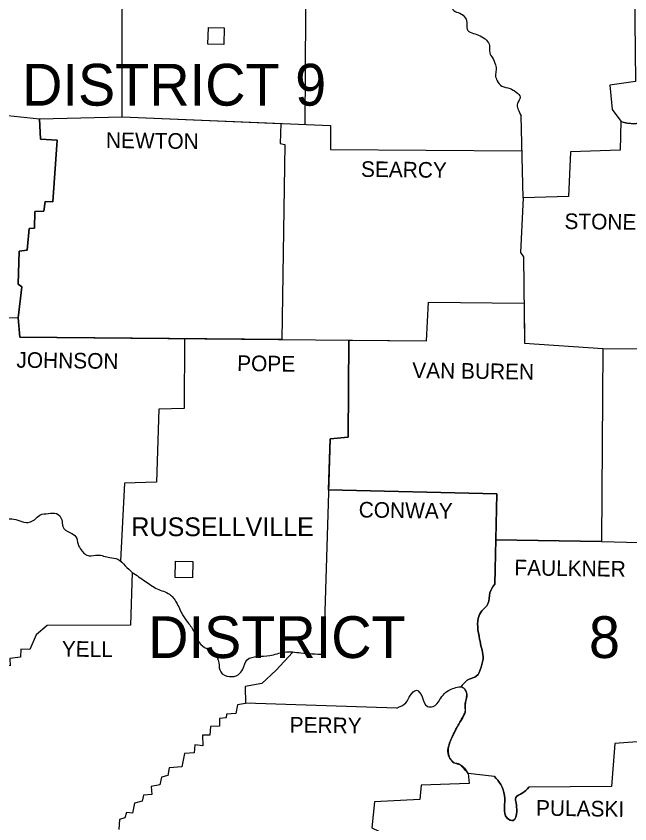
# Model space of a CAD drawing. Extents: x 840176 to 859715, y 1589036 to 1600368.
# Drawn here: x 854218 to 855136, y 1597581 to 1598788 of the extents above; entities that cross this region are included whole.
import ezdxf

# ---------------------------------------------------------------- set-up
doc = ezdxf.new("R2010")
doc.units = 0
doc.layers.add('DSN_DRFT_Border', color=7, linetype='Continuous')
doc.layers.add('SHET_Stamp-Prelim', color=7, linetype='Continuous')

msp = doc.modelspace()

# ---------------------------------------------------------------- linework, layer by layer
at = {"layer": 'DSN_DRFT_Border'}
msp.add_line((854885, 1597788.1), (854883.1, 1597786), dxfattribs=at)
for points in [[(853989.1, 1598788.7), (854127.2, 1598784.3), (854130.3, 1598766.8), (854149.3, 1598766.2), (854148.7, 1598755.6), (854161.4, 1598752.2), (854162.7, 1598692.1), (854179.8, 1598688.4), (854181, 1598664.7), (854204.7, 1598661.6), (854205.9, 1598639.5), (854253.3, 1598634.4), (854376.5, 1598637.7), (854377.4, 1598959.2)], [(854651.9, 1598959.7), (854650, 1598626.2)], [(855150.4, 1598960.7), (855151.7, 1598827.2), (855142.7, 1598826.6), (855143.9, 1598690.3), (855105.9, 1598684.7), (855109.1, 1598648.3), (855122.1, 1598631.1), (855121.2, 1598587.9), (855046.8, 1598585.1), (855044, 1598518.5), (854976.2, 1598516.3), (854972.4, 1598434.8), (854976.5, 1598428.5), (854978.3, 1598299.1), (855095.1, 1598291.3), (855093.5, 1598002.8), (855186.9, 1598000.3), (855186.9, 1597706.5), (855113.4, 1597700.9), (855108.1, 1597636.8), (854984.6, 1597635.9)], [(853529.5, 1598628.3), (853633.9, 1598628), (853636.4, 1598663.8), (853674.1, 1598663.8), (853677.5, 1598722.3), (853891.3, 1598714.9), (853897.5, 1598731), (853987.6, 1598733), (853941.7, 1598604.7), (853932.7, 1598401.5), (853926.1, 1598401.2), (853923, 1598339.8), (853955.1, 1598337), (853960.1, 1598342), (854221.2, 1598337), (854224, 1598308.1)], [(854253.3, 1598634.4), (854254.5, 1598604.1), (854279.7, 1598602.8), (854273.1, 1598510.7), (854261.6, 1598511), (854259.5, 1598496.4), (854246.4, 1598496.1), (854245.8, 1598471.2), (854237.7, 1598470.6), (854234.9, 1598438.2), (854222.7, 1598436.6), (854221.2, 1598387.5), (854226.8, 1598383.4), (854221.2, 1598337)], [(854376.5, 1598637.7), (854688.3, 1598624.6), (854688, 1598588.8), (854974.4, 1598586.9)], [(854613.7, 1598627.7), (854612.7, 1598597.8), (854620.1, 1598596), (854615.4, 1598304.7)], [(854976.2, 1598516.3), (854973.1, 1598639.2)], [(854224, 1598308.1), (854831.8, 1598302.8), (854834.9, 1598360.7), (854977.5, 1598358.8)], [(854469.8, 1598306), (854469.2, 1598201.4), (854431.5, 1598200.7), (854428.1, 1598091.8), (854380.2, 1598089.9), (854374.4, 1597974)], [(854715.4, 1598303.8), (854714.4, 1598158.7), (854687.7, 1598156.2), (854677.7, 1597834.1)], [(855095.1, 1598291.3), (855376.7, 1598290.1), (855400.7, 1598301.3), (855399.1, 1598087.5), (855382.9, 1598080.3), (855368, 1598067.5), (855363.3, 1598062.6), (855362.4, 1598001.2), (855186.9, 1598000.3)], [(854685.3, 1598080.3), (854937, 1598074.1), (854933.8, 1597939)], [(854935.4, 1598005.3), (855093.5, 1598002.8)], [(854391.7, 1597956.7), (854389.2, 1597878), (854264.7, 1597877.4), (854248.2, 1597863.4), (854238.6, 1597841.6), (854225.2, 1597842.2), (854224.6, 1597830.1), (854208.7, 1597828.2), (854209.3, 1597817), (854130, 1597818.9), (854126.9, 1597810.2), (854094.2, 1597808.9), (854093.9, 1597712.9)], [(854631.4, 1597837.3), (854606.8, 1597810.8), (854585.6, 1597790.6), (854560.7, 1597786.5), (854561, 1597760.7), (854548.9, 1597759.1), (854546.7, 1597746.1), (854532.7, 1597744.8), (854532.1, 1597739.2), (854522.4, 1597738.6), (854522.1, 1597727.1), (854508.7, 1597726.4), (854507.8, 1597713.4), (854496.6, 1597713.4), (854497.2, 1597697.8), (854485.4, 1597699.1), (854484.5, 1597686.9), (854469.8, 1597686), (854465.8, 1597666.1), (854447.1, 1597664.5), (854445.2, 1597653.3), (854435.3, 1597650.8), (854432.8, 1597639.3), (854420.3, 1597636.8), (854421.3, 1597625), (854408.8, 1597623.7), (854406.7, 1597615), (854395.1, 1597611.9), (854392.3, 1597597), (854383.3, 1597597.9), (854380.8, 1597590.1), (854372.7, 1597587.3), (854371.8, 1597572.4)], [(854787.3, 1597754.1), (854561, 1597761.6)], [(854933.2, 1597651.8), (854894, 1597656.4), (854895.6, 1597641.5), (854823.7, 1597638.7), (854821.5, 1597617.5), (854754, 1597613.8), (854750.2, 1597575.2), (854760.2, 1597570.2), (854760.2, 1597545)]]:
    msp.add_lwpolyline(points, dxfattribs=at)
for points in [[(854505, 1598746), (854505.6, 1598770.9), (854529.3, 1598770.3), (854528.6, 1598745.4)], [(854455.8, 1597949.3), (854456.4, 1597973.6), (854482.3, 1597972.9), (854481.7, 1597948.7)]]:
    msp.add_lwpolyline(points, close=True, dxfattribs=at)
for points in [[(854891.5, 1598863.6), (854881.6, 1598855.8), (854873.2, 1598848.1), (854859.8, 1598838.4), (854858.2, 1598829.7), (854862.6, 1598821.3), (854866.9, 1598814.1), (854868.8, 1598804.2), (854872.5, 1598796.1), (854881.6, 1598792.3), (854889.7, 1598785.5), (854892.1, 1598775.9), (854893.4, 1598766.5), (854901.8, 1598762.2), (854911.7, 1598758.4), (854921.4, 1598751.9), (854925.8, 1598744.1), (854926.4, 1598733.2), (854930.4, 1598725.4), (854934.8, 1598715.2), (854935.7, 1598707.1), (854934.8, 1598699), (854937.3, 1598691.2), (854944.1, 1598683.4), (854956.6, 1598679.7), (854965.6, 1598674.4), (854971.8, 1598666.6), (854967.5, 1598657.6), (854968.4, 1598649.2), (854973.1, 1598639.2)], [(854102.3, 1598023), (854120.6, 1598028.9), (854133.7, 1598030.5), (854147.1, 1598028), (854160.8, 1598022.4), (854175.1, 1598024), (854186, 1598027.7), (854197.2, 1598034.9), (854209, 1598037), (854220.9, 1598034.9), (854233, 1598031.4), (854245.8, 1598035.5), (854253.5, 1598042.3), (854266.6, 1598044.8), (854278.4, 1598044.8), (854286.5, 1598035.5), (854288.1, 1598025.2), (854298.7, 1598016.2), (854307.7, 1598010), (854310.8, 1597998.8), (854315.5, 1597990.4), (854320.4, 1597984.8), (854327.6, 1597981.6), (854339.7, 1597982.6), (854358.4, 1597978.8), (854370.2, 1597976.4), (854381.4, 1597966.7), (854391.7, 1597956.7)], [(854391.7, 1597956.7), (854411, 1597943.7), (854429.1, 1597932.2), (854447.4, 1597924.1), (854457.7, 1597912.2), (854467, 1597893.3), (854475.1, 1597881.7), (854484.5, 1597867.4), (854491.9, 1597851.9), (854503.1, 1597842.8), (854515.3, 1597835.4), (854521.2, 1597821.7), (854524, 1597808), (854537.4, 1597801.1), (854550.1, 1597803.9), (854557, 1597812.3), (854563.8, 1597826.3), (854578.4, 1597831), (854597.4, 1597832.6), (854619.2, 1597837.6), (854643.8, 1597836.6), (854677.7, 1597834.1)], [(854933.8, 1597939), (854926.4, 1597926.2), (854923.6, 1597909.8), (854914.5, 1597899.2), (854908.9, 1597887.7), (854908.6, 1597871.5), (854911.1, 1597857.2), (854913.9, 1597843.8), (854916.4, 1597831), (854913.3, 1597815.1), (854906.1, 1597801.5), (854895.6, 1597797.4), (854885, 1597788.1)], [(854787.3, 1597754.1), (854800.6, 1597761.9), (854807.8, 1597773.4), (854816.5, 1597780.6), (854825.2, 1597770.6), (854833, 1597756.6), (854841.4, 1597756.3), (854851.7, 1597766.6), (854858.2, 1597775.3), (854866.6, 1597781.5), (854875.3, 1597784.6), (854884.4, 1597785.6), (854891.8, 1597775), (854889.3, 1597758.5), (854889.3, 1597747.9), (854883.4, 1597736.1), (854876.6, 1597724), (854869.7, 1597710.3), (854864.4, 1597695.9), (854865.4, 1597681.3), (854873.2, 1597672.3), (854881.6, 1597669.5), (854894, 1597656.4)], [(854933.2, 1597651.8), (854942.6, 1597639.9), (854948.2, 1597623.4), (854948.2, 1597604.8), (854952.2, 1597589.5), (854961.2, 1597586.1), (854966.5, 1597599.5), (854965.6, 1597612.2), (854965.3, 1597620.3), (854974.9, 1597626.9), (854984.6, 1597635.9)]]:
    msp.add_spline(points, degree=3, dxfattribs=at)
msp.add_open_spline([(855122.1, 1598631.1), (855123.9, 1598630.3), (855125.6, 1598629.6), (855127.5, 1598629.1), (855129.3, 1598628.7), (855131.1, 1598628.3), (855133, 1598628.1), (855134.8, 1598627.9), (855136.6, 1598627.8), (855138.5, 1598627.6), (855140.3, 1598627.5), (855142.1, 1598627.4), (855143.9, 1598627.4), (855145.1, 1598627.4), (855146.3, 1598627.9), (855147.4, 1598628.6), (855148.6, 1598629.3), (855149.7, 1598630.3), (855150.8, 1598631.1), (855151.9, 1598631.8), (855153, 1598632.4), (855154.2, 1598633), (855154.7, 1598633.2), (855155.3, 1598633.2), (855155.8, 1598633.1), (855156.3, 1598633), (855156.8, 1598632.8), (855157.3, 1598632.4), (855159.7, 1598630.3), (855161.5, 1598628.2), (855162.9, 1598625.6), (855163.6, 1598624.3), (855164.2, 1598623), (855164.8, 1598621.7), (855165.4, 1598620.4), (855166, 1598619.1), (855166.6, 1598617.8), (855168.2, 1598614.1), (855169.7, 1598610.5), (855171.3, 1598606.9), (855172.5, 1598604.2), (855173.7, 1598601.5), (855175, 1598598.9), (855175.7, 1598597.5), (855176.4, 1598596.3), (855177.2, 1598595), (855177.6, 1598594.4), (855178, 1598593.8), (855178.4, 1598593.1), (855178.8, 1598592.5), (855179.2, 1598591.9), (855179.7, 1598591.3), (855180.4, 1598590.4), (855181.3, 1598589.7), (855182.4, 1598589.2), (855183.5, 1598588.8), (855184.7, 1598588.4), (855185.8, 1598588.2), (855187, 1598587.9), (855188.2, 1598587.7), (855189.4, 1598587.4), (855190, 1598587.2), (855190.6, 1598587), (855191.2, 1598586.8), (855191.7, 1598586.6), (855192.3, 1598586.3), (855192.8, 1598586), (855194.7, 1598584.9), (855196.5, 1598583.6), (855198.2, 1598582.3), (855199, 1598581.6), (855199.8, 1598580.9), (855200.6, 1598580.1), (855201.4, 1598579.3), (855202.1, 1598578.5), (855202.7, 1598577.6), (855203.2, 1598576.9), (855203.5, 1598576.2), (855203.7, 1598575.4), (855204, 1598574.6), (855204.1, 1598573.7), (855204, 1598572.9), (855203.9, 1598571.7), (855203.6, 1598570.4), (855203.1, 1598569.3), (855202.9, 1598568.9), (855202.7, 1598568.6), (855202.4, 1598568.3), (855201.8, 1598567.5), (855201.1, 1598566.7), (855200.4, 1598566), (855199.6, 1598565.3), (855198.9, 1598564.6), (855198.1, 1598563.9), (855197.4, 1598563.2), (855196.6, 1598562.5), (855195.8, 1598561.8), (855195.1, 1598561.1), (855194.4, 1598560.3), (855193.7, 1598559.6), (855193.4, 1598559.2), (855193.1, 1598558.8), (855192.8, 1598558.5), (855191.8, 1598557.4), (855190.7, 1598556.4), (855189.7, 1598555.3), (855189.1, 1598554.6), (855188.6, 1598553.9), (855188.1, 1598553), (855187.9, 1598552.6), (855187.8, 1598552.3), (855187.7, 1598551.8), (855187.5, 1598551.4), (855187.5, 1598551), (855187.5, 1598550.5), (855187.5, 1598549.7), (855187.6, 1598548.8), (855187.7, 1598547.9), (855187.9, 1598547), (855188.1, 1598546.1), (855188.3, 1598545.3), (855188.6, 1598544.4), (855188.9, 1598543.5), (855189.1, 1598542.6), (855189.3, 1598541.7), (855189.5, 1598540.9), (855189.7, 1598540), (855190.1, 1598537.6), (855190.4, 1598535.2), (855190.8, 1598532.8), (855191.2, 1598530.4), (855191.5, 1598528), (855191.8, 1598525.6), (855192.4, 1598521.2), (855192.9, 1598516.6), (855191.8, 1598512.3), (855190.8, 1598508), (855189.5, 1598503.8), (855188.4, 1598499.5), (855187.5, 1598495.8), (855186.5, 1598492.1), (855185.6, 1598488.3), (855185.4, 1598487.4), (855185.3, 1598486.6), (855185.3, 1598485.7), (855185.3, 1598484.8), (855185.4, 1598484), (855185.6, 1598483.1), (855185.9, 1598482.2), (855186.2, 1598481.4), (855186.7, 1598480.6), (855186.9, 1598480.1), (855187.2, 1598479.7), (855187.4, 1598479.3), (855187.7, 1598478.8), (855188.1, 1598478.4), (855188.4, 1598478), (855188.7, 1598477.6), (855189.1, 1598477.4), (855189.5, 1598477.1), (855189.9, 1598476.9), (855190.4, 1598476.7), (855190.8, 1598476.7), (855191.7, 1598476.6), (855192.6, 1598476.7), (855193.5, 1598477.1), (855195.3, 1598478), (855197, 1598478.9), (855198.7, 1598479.9), (855199.2, 1598480.2), (855199.7, 1598480.5), (855200.1, 1598480.8), (855200.6, 1598481.1), (855201, 1598481.4), (855201.5, 1598481.8), (855202.4, 1598482.6), (855203.3, 1598483.4), (855204.2, 1598484.2), (855205, 1598484.9), (855206, 1598485.7), (855206.9, 1598486.4), (855207.8, 1598487.1), (855208.8, 1598487.6), (855209.9, 1598488), (855213.5, 1598489.3), (855217.8, 1598489.3), (855221.4, 1598488), (855223.3, 1598487.3), (855225.2, 1598486.4), (855227, 1598485.3), (855228.8, 1598484.3), (855230.6, 1598483.3), (855232.3, 1598482.1), (855233.4, 1598481.3), (855234.3, 1598480.3), (855235.2, 1598479.3), (855236.1, 1598478.2), (855236.8, 1598477.1), (855237.7, 1598476), (855238.5, 1598474.9), (855239.4, 1598474), (855240.3, 1598473), (855240.8, 1598472.6), (855241.3, 1598472.3), (855241.8, 1598472), (855242.1, 1598471.9), (855242.3, 1598471.8), (855242.6, 1598471.7), (855242.9, 1598471.6), (855243.2, 1598471.5), (855243.5, 1598471.5), (855245.4, 1598471.3), (855247.4, 1598471.4), (855249.2, 1598471.9), (855251.2, 1598472.5), (855253.1, 1598473.1), (855255, 1598473.7), (855258.2, 1598474.7), (855261.4, 1598475.7), (855264.7, 1598476.8), (855266.8, 1598477.5), (855269, 1598478.2), (855271.2, 1598478.8), (855272.3, 1598479.2), (855273.4, 1598479.4), (855274.5, 1598479.7), (855275, 1598479.8), (855275.6, 1598479.9), (855276.1, 1598480), (855276.6, 1598480.1), (855277.2, 1598480.2), (855277.7, 1598480.2), (855279.4, 1598480.3), (855281.1, 1598479.7), (855282.6, 1598478.8), (855284.1, 1598477.7), (855285.6, 1598476.6), (855287.1, 1598475.5), (855288.5, 1598474.5), (855289.9, 1598473.4), (855291.2, 1598472.4), (855292.6, 1598471.3), (855293.9, 1598470.2), (855295.2, 1598469), (855296, 1598468.2), (855296.9, 1598467.3), (855297.7, 1598466.5), (855298.5, 1598465.6), (855299.3, 1598464.7), (855300.1, 1598463.8), (855300.9, 1598463), (855301.7, 1598462.1), (855302.5, 1598461.2), (855303.4, 1598460.3), (855304.2, 1598459.5), (855305.1, 1598458.7), (855308, 1598456.1), (855311.1, 1598453.9), (855314.5, 1598451.9), (855318.2, 1598449.5), (855322.1, 1598447.6), (855326.3, 1598446), (855327.5, 1598445.5), (855328.7, 1598445.1), (855329.9, 1598444.8), (855331.2, 1598444.5), (855332.4, 1598444.3), (855333.7, 1598444), (855335, 1598443.8), (855336.2, 1598443.5), (855337.5, 1598443.3), (855338.8, 1598443), (855340, 1598442.6), (855341.2, 1598442.2), (855343.9, 1598441.4), (855346.5, 1598440.3), (855349, 1598438.9), (855350.3, 1598438.2), (855351.4, 1598437.4), (855352.4, 1598436.4), (855352.9, 1598435.9), (855353.3, 1598435.3), (855353.8, 1598434.8), (855354, 1598434.5), (855354.2, 1598434.2), (855354.4, 1598433.9), (855354.6, 1598433.6), (855354.7, 1598433.2), (855354.9, 1598432.9), (855355.2, 1598432.3), (855355.5, 1598431.6), (855355.8, 1598430.9), (855356.4, 1598429), (855356.9, 1598427), (855357, 1598425), (855357.1, 1598423.7), (855357.2, 1598422.4), (855357.2, 1598421), (855357.1, 1598419.7), (855357.1, 1598418.4), (855357.1, 1598417), (855357.1, 1598414.7), (855357.1, 1598412.5), (855357, 1598410.2), (855357, 1598407.9), (855356.9, 1598405.6), (855356.8, 1598403.3), (855356.4, 1598397.6), (855355.9, 1598391.9), (855355.5, 1598386.2), (855355.1, 1598380.1), (855354.7, 1598374), (855354.3, 1598367.9), (855354.2, 1598366.3), (855354.1, 1598364.8), (855354, 1598363.2), (855353.9, 1598361.7), (855353.9, 1598360.1), (855353.9, 1598358.6), (855353.9, 1598357), (855354, 1598355.5), (855354.4, 1598354), (855354.7, 1598352.4), (855355.1, 1598350.9), (855355.8, 1598349.5), (855356.9, 1598347.5), (855357.9, 1598345.5), (855358.9, 1598343.5), (855360, 1598341.5), (855361, 1598339.6), (855362.1, 1598337.7), (855363.3, 1598335.3), (855364.6, 1598332.9), (855365.8, 1598330.5), (855367.1, 1598328.1), (855368.3, 1598325.8), (855369.5, 1598323.4), (855370.6, 1598321.3), (855371.2, 1598319.1), (855371.5, 1598316.8), (855371.6, 1598315.7), (855371.7, 1598314.5), (855371.8, 1598313.4), (855371.9, 1598312.3), (855372, 1598311.1), (855372, 1598310), (855372.2, 1598306.7), (855372.3, 1598303.3), (855372.3, 1598300), (855372.3, 1598296.7), (855372, 1598293.4), (855371.5, 1598290.1)], degree=3, dxfattribs=at)
at = {"layer": 'SHET_Stamp-Prelim'}
for p, q in [((854933.8, 1597939), (854935.4, 1598005.3)), ((854933.2, 1597651.8), (854894, 1597656.4))]:
    msp.add_line(p, q, dxfattribs=at)
for points in [[(854615.4, 1598304.7), (854224, 1598308.1), (854221.2, 1598337), (854226.8, 1598383.4), (854221.2, 1598387.5), (854222.7, 1598436.6), (854234.9, 1598438.2), (854237.7, 1598470.6), (854245.8, 1598471.2), (854246.4, 1598496.1), (854259.5, 1598496.4), (854261.6, 1598511), (854273.1, 1598510.7), (854279.7, 1598602.8), (854254.5, 1598604.1), (854253.3, 1598634.4), (854376.5, 1598637.7), (854613.7, 1598627.7), (854612.7, 1598597.8), (854620.1, 1598596)], [(854937, 1598074.1), (854685.3, 1598080.3), (854687.7, 1598156.2), (854714.4, 1598158.7), (854715.4, 1598303.8), (854831.8, 1598302.8), (854834.9, 1598360.7), (854977.5, 1598358.8), (854978.3, 1598299.1), (855095.1, 1598291.3), (855093.5, 1598002.8), (854935.4, 1598005.3)]]:
    msp.add_lwpolyline(points, close=True, dxfattribs=at)
for points in [[(854935.4, 1598005.3), (855093.5, 1598002.8)], [(855093.5, 1598002.8), (855186.9, 1598000.3), (855186.9, 1597706.5), (855113.4, 1597700.9), (855108.1, 1597636.8), (854984.6, 1597635.9)]]:
    msp.add_lwpolyline(points, dxfattribs=at)
for points in [[(854885, 1597788.1), (854895.6, 1597797.4), (854906.1, 1597801.5), (854913.3, 1597815.1), (854916.4, 1597831), (854913.9, 1597843.8), (854911.1, 1597857.2), (854908.6, 1597871.5), (854908.9, 1597887.7), (854914.5, 1597899.2), (854923.6, 1597909.8), (854926.4, 1597926.2), (854933.8, 1597939)], [(854894, 1597656.4), (854881.6, 1597669.5), (854880.7, 1597670.2), (854879.7, 1597670.6), (854877.5, 1597671), (854875.3, 1597671.4), (854873.2, 1597672.3), (854871.9, 1597673.2), (854870.7, 1597674.2), (854868.6, 1597676.3), (854866.8, 1597678.6), (854865.4, 1597681.3), (854864.7, 1597683.1), (854864.2, 1597685), (854863.6, 1597688.7), (854863.7, 1597692.4), (854864, 1597694.2), (854864.4, 1597695.9), (854865.6, 1597699.6), (854866.8, 1597703.2), (854868.2, 1597706.8), (854869.7, 1597710.3), (854871.4, 1597713.7), (854873.1, 1597717.2), (854876.6, 1597724), (854880, 1597730), (854883.4, 1597736.1), (854885, 1597739), (854886.6, 1597741.9), (854888.7, 1597746.3), (854889.3, 1597747.9), (854889.7, 1597749.2), (854889.8, 1597750.5), (854889.7, 1597753.2), (854889.4, 1597755.8), (854889.3, 1597758.5), (854889.5, 1597760.6), (854889.9, 1597762.6), (854890.8, 1597766.8), (854891.6, 1597770.9), (854891.8, 1597775), (854891.6, 1597776.6), (854891.2, 1597778.2), (854889.6, 1597781.2), (854885.9, 1597784.8), (854884.4, 1597785.6), (854884, 1597785.7), (854883.7, 1597785.8), (854883.1, 1597786)], [(854984.6, 1597635.9), (854974.9, 1597626.9), (854965.3, 1597620.3), (854965.6, 1597612.2), (854966.5, 1597599.5), (854961.2, 1597586.1), (854952.2, 1597589.5), (854948.2, 1597604.8), (854948.2, 1597623.4), (854942.6, 1597639.9), (854933.2, 1597651.8)]]:
    msp.add_spline(points, degree=3, dxfattribs=at)

# ---------------------------------------------------------------- texts
at = {"layer": 'DSN_DRFT_Border'}
for s, height, p in [('DISTRICT 9', 62.43, (854227.2, 1598654.2)), ('RUSSELLVILLE', 28.009, (854390.5, 1598010.9)), ('DISTRICT', 62.43, (854415.6, 1597828.8)), ('8', 62.4, (855074.5, 1597828.8))]:
    msp.add_text(s, height=height, dxfattribs=at).set_placement(p)
for s, rotation, p in [('NEWTON', 359.303, (854352.4, 1598591)), ('SEARCY', 359.2838, (854733.6, 1598547.8)), ('STONE', 359.3139, (855037.8, 1598469.9)), ('JOHNSON', 359.2575, (854218.5, 1598262.7)), ('POPE', 359.3389, (854548.5, 1598257.7)), ('VAN BUREN', 359.2547, (854810.3, 1598247.2)), ('CONWAY', 359.1737, (854730.2, 1598038.9)), ('FAULKNER', 359.2447, (854962.9, 1597952.4)), ('YELL', 359.3097, (854286.4, 1597831)), ('PERRY', 359.2992, (854627, 1597717.5)), ('PULASKI', 359.1854, (854995.2, 1597593.3))]:
    msp.add_text(s, height=23.34, rotation=rotation, dxfattribs=at).set_placement(p)

doc.saveas('drawing.dxf')
